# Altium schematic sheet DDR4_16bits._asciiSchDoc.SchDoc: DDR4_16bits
size A3; Date: Not used; ApprovedBy: Not used; CheckedBy: Not used; Author: Not used; CompanyName: STMicroelectronics; DrawnBy: Not used; Engineer: Not used; Organization: Not used; Address1: Not used; Address2: Not used; Address3: Not used; Address4: Not used; DocumentNumber: 6; Revision: Not used; SheetNumber: 6; SheetTotal: 7
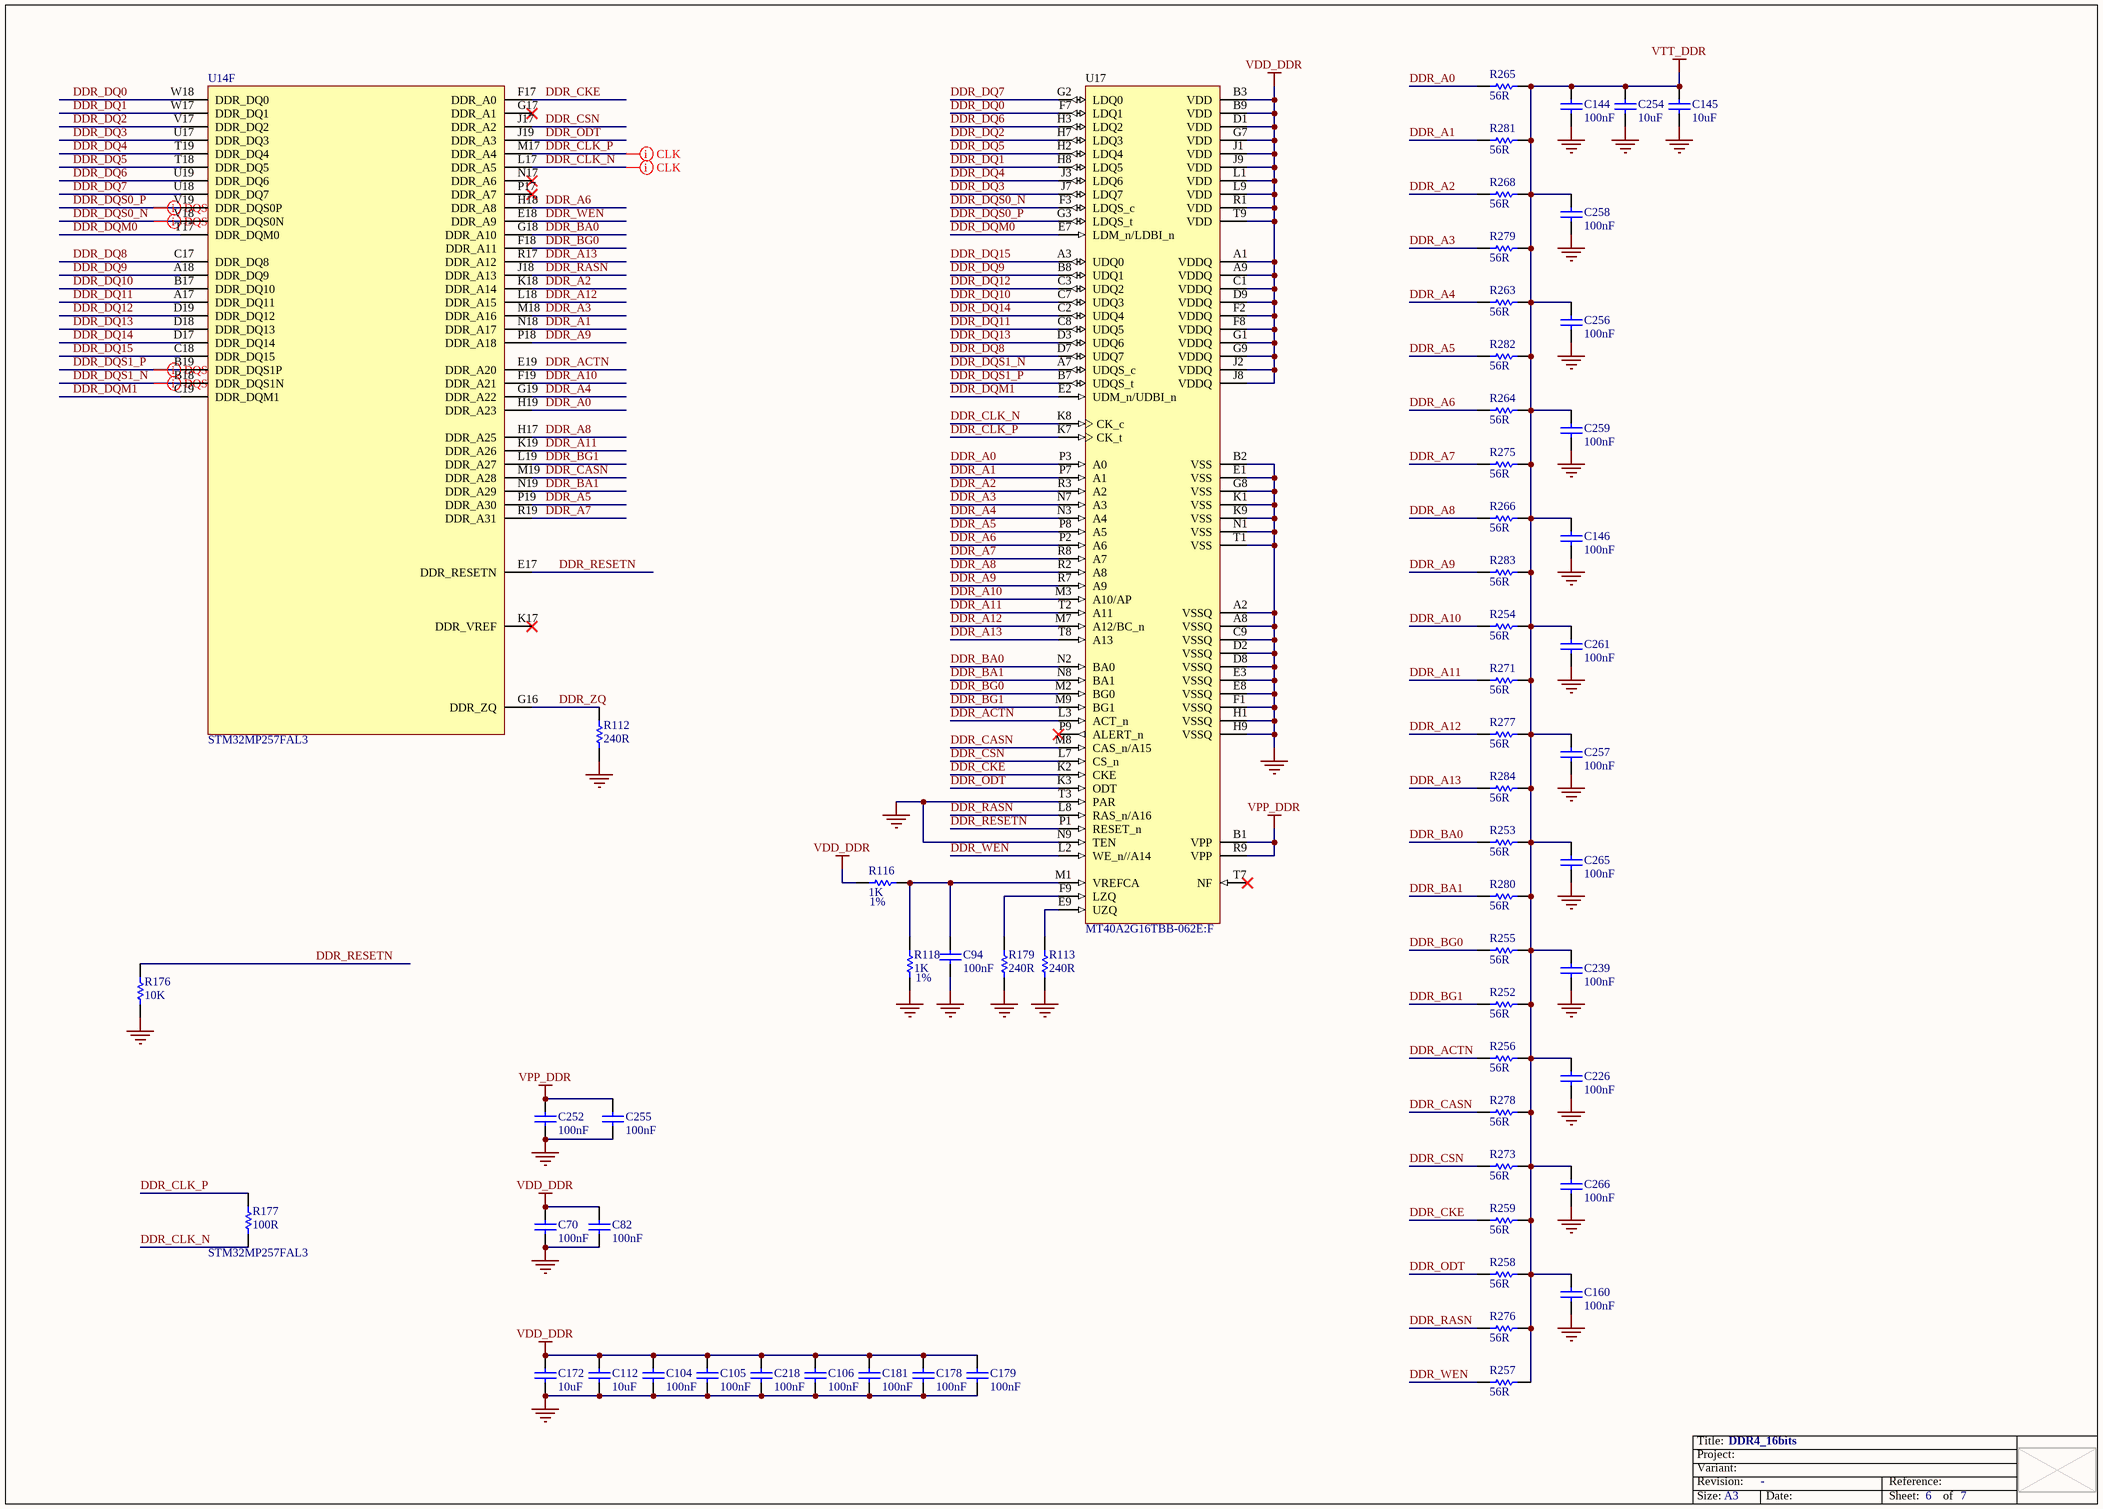
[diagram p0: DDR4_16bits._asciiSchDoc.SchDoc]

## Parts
C70  value 100nF  [C0402]  (hidden comment: Capacitor)
C82  value 100nF  [C0402]  (hidden comment: Capacitor)
C94  value 100nF  [C0402]  (hidden comment: Capacitor)
C104  value 100nF  [C0402]  (hidden comment: Capacitor)
C105  value 100nF  [C0402]  (hidden comment: Capacitor)
C106  value 100nF  [C0402]  (hidden comment: Capacitor)
C112  value 10uF  [C0603]  (hidden comment: Capacitor)
C144  value 100nF  [C0402]  (hidden comment: Capacitor)
C145  value 10uF  [C0402]  (hidden comment: Capacitor)
C146  value 100nF  [C0402]  (hidden comment: Capacitor)
C160  value 100nF  [C0402]  (hidden comment: Capacitor)
C172  value 10uF  [C0603]  (hidden comment: Capacitor)
C178  value 100nF  [C0402]  (hidden comment: Capacitor)
C179  value 100nF  [C0402]  (hidden comment: Capacitor)
C181  value 100nF  [C0402]  (hidden comment: Capacitor)
C218  value 100nF  [C0402]  (hidden comment: Capacitor)
C226  value 100nF  [C0402]  (hidden comment: Capacitor)
C239  value 100nF  [C0402]  (hidden comment: Capacitor)
C252  value 100nF  [C0402]  (hidden comment: Capacitor)
C254  value 10uF  [C0402]  (hidden comment: Capacitor)
C255  value 100nF  [C0402]  (hidden comment: Capacitor)
C256  value 100nF  [C0402]  (hidden comment: Capacitor)
C257  value 100nF  [C0402]  (hidden comment: Capacitor)
C258  value 100nF  [C0402]  (hidden comment: Capacitor)
C259  value 100nF  [C0402]  (hidden comment: Capacitor)
C261  value 100nF  [C0402]  (hidden comment: Capacitor)
C265  value 100nF  [C0402]  (hidden comment: Capacitor)
C266  value 100nF  [C0402]  (hidden comment: Capacitor)
R112  value 240R  [R0201_H0P23]  (hidden comment: Resistor)
R113  value 240R  [R0201_H0P23]  (hidden comment: Resistor)
R116  value 1K  [R0402]  (hidden comment: Resistor)
R118  value 1K  [R0402]  (hidden comment: Resistor)
R176  value 10K  [R0402]  (hidden comment: Resistor)
R177  value 100R  [R0402]  (hidden comment: Resistor)
R179  value 240R  [R0201_H0P23]  (hidden comment: Resistor)
R252  value 56R  [R0402]  (hidden comment: Resistor)
R253  value 56R  [R0402]  (hidden comment: Resistor)
R254  value 56R  [R0402]  (hidden comment: Resistor)
R255  value 56R  [R0402]  (hidden comment: Resistor)
R256  value 56R  [R0402]  (hidden comment: Resistor)
R257  value 56R  [R0402]  (hidden comment: Resistor)
R258  value 56R  [R0402]  (hidden comment: Resistor)
R259  value 56R  [R0402]  (hidden comment: Resistor)
R263  value 56R  [R0402]  (hidden comment: Resistor)
R264  value 56R  [R0402]  (hidden comment: Resistor)
R265  value 56R  [R0402]  (hidden comment: Resistor)
R266  value 56R  [R0402]  (hidden comment: Resistor)
R268  value 56R  [R0402]  (hidden comment: Resistor)
R271  value 56R  [R0402]  (hidden comment: Resistor)
R273  value 56R  [R0402]  (hidden comment: Resistor)
R275  value 56R  [R0402]  (hidden comment: Resistor)
R276  value 56R  [R0402]  (hidden comment: Resistor)
R277  value 56R  [R0402]  (hidden comment: Resistor)
R278  value 56R  [R0402]  (hidden comment: Resistor)
R279  value 56R  [R0402]  (hidden comment: Resistor)
R280  value 56R  [R0402]  (hidden comment: Resistor)
R281  value 56R  [R0402]  (hidden comment: Resistor)
R282  value 56R  [R0402]  (hidden comment: Resistor)
R283  value 56R  [R0402]  (hidden comment: Resistor)
R284  value 56R  [R0402]  (hidden comment: Resistor)
U14  STM32MP257FAL3  [ICC_VFBGA361_10X10_P050]  (part F of 8)
U17  MT40A2G16TBB-062E:F  [ICC_FBGA96_TBB_7P5X13_P080]

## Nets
GND: C70.1 C82.1 C94.1 C104.1 C105.1 C106.1 C112.1 C144.1 C145.1 C146.1 C160.1 C172.1 C178.1 C179.1 C181.1 C218.1 C226.1 C239.1 C252.1 C254.1 C255.1 C256.1 C257.1 C258.1 C259.1 C261.1 C265.1 C266.1 R112.1 R113.1 R118.1 R176.1 R179.1 U17.A2(VSSQ) U17.A8(VSSQ) U17.B2(VSS) U17.C9(VSSQ) U17.D2(VSSQ) U17.D8(VSSQ) U17.E1(VSS) U17.E3(VSSQ) U17.E8(VSSQ) U17.F1(VSSQ) U17.G8(VSS) U17.H1(VSSQ) U17.H9(VSSQ) U17.K1(VSS) U17.K9(VSS) U17.N1(VSS) U17.N9(TEN) U17.T1(VSS) U17.T3(PAR)
VDD_DDR: C70.2 C82.2 C104.2 C105.2 C106.2 C112.2 C172.2 C178.2 C179.2 C181.2 C218.2 R116.1 U17.A1(VDDQ) U17.A9(VDDQ) U17.B3(VDD) U17.B9(VDD) U17.C1(VDDQ) U17.D1(VDD) U17.D9(VDDQ) U17.F2(VDDQ) U17.F8(VDDQ) U17.G1(VDDQ) U17.G7(VDD) U17.G9(VDDQ) U17.J1(VDD) U17.J2(VDDQ) U17.J8(VDDQ) U17.J9(VDD) U17.L1(VDD) U17.L9(VDD) U17.R1(VDD) U17.T9(VDD)
VPP_DDR: C252.2 C255.2 U17.B1(VPP) U17.R9(VPP)
VTT_DDR: C144.2 C145.2 C146.2 C160.2 C226.2 C239.2 C254.2 C256.2 C257.2 C258.2 C259.2 C261.2 C265.2 C266.2 R252.2 R253.2 R254.2 R255.2 R256.2 R257.2 R258.2 R259.2 R263.2 R264.2 R265.2 R266.2 R268.2 R271.2 R273.2 R275.2 R276.2 R277.2 R278.2 R279.2 R280.2 R281.2 R282.2 R283.2 R284.2
DDR_A0: R265.1 U14.H19(DDR_A23) U17.P3(A0)
DDR_A1: R281.1 U14.N18(DDR_A17) U17.P7(A1)
DDR_A2: R268.1 U14.K18(DDR_A14) U17.R3(A2)
DDR_A3: R279.1 U14.M18(DDR_A16) U17.N7(A3)
DDR_A4: R263.1 U14.G19(DDR_A22) U17.N3(A4)
DDR_A5: R282.1 U14.P19(DDR_A30) U17.P8(A5)
DDR_A6: R264.1 U14.H18(DDR_A8) U17.P2(A6)
DDR_A7: R275.1 U14.R19(DDR_A31) U17.R8(A7)
DDR_A8: R266.1 U14.H17(DDR_A25) U17.R2(A8)
DDR_A9: R283.1 U14.P18(DDR_A18) U17.R7(A9)
DDR_A10: R254.1 U14.F19(DDR_A21) U17.M3(A10/AP)
DDR_A11: R271.1 U14.K19(DDR_A26) U17.T2(A11)
DDR_A12: R277.1 U14.L18(DDR_A15) U17.M7(A12/BC_n)
DDR_A13: R284.1 U14.R17(DDR_A12) U17.T8(A13)
DDR_ACTN: R256.1 U14.E19(DDR_A20) U17.L3(ACT_n)
DDR_BA0: R253.1 U14.G18(DDR_A10) U17.N2(BA0)
DDR_BA1: R280.1 U14.N19(DDR_A29) U17.N8(BA1)
DDR_BG0: R255.1 U14.F18(DDR_A11) U17.M2(BG0)
DDR_BG1: R252.1 U14.L19(DDR_A27) U17.M9(BG1)
DDR_CASN: R278.1 U14.M19(DDR_A28) U17.M8(CAS_n/A15)
DDR_CKE: R259.1 U14.F17(DDR_A0) U17.K2(CKE)
DDR_CLK_N: R177.2 U14.L17(DDR_A5) U17.K8(CK_c)
DDR_CLK_P: R177.1 U14.M17(DDR_A4) U17.K7(CK_t)
DDR_CSN: R273.1 U14.J17(DDR_A2) U17.L7(CS_n)
DDR_DQ0: U14.W18(DDR_DQ0) U17.F7(LDQ1)
DDR_DQ1: U14.W17(DDR_DQ1) U17.H8(LDQ5)
DDR_DQ2: U14.V17(DDR_DQ2) U17.H7(LDQ3)
DDR_DQ3: U14.U17(DDR_DQ3) U17.J7(LDQ7)
DDR_DQ4: U14.T19(DDR_DQ4) U17.J3(LDQ6)
DDR_DQ5: U14.T18(DDR_DQ5) U17.H2(LDQ4)
DDR_DQ6: U14.U19(DDR_DQ6) U17.H3(LDQ2)
DDR_DQ7: U14.U18(DDR_DQ7) U17.G2(LDQ0)
DDR_DQ8: U14.C17(DDR_DQ8) U17.D7(UDQ7)
DDR_DQ9: U14.A18(DDR_DQ9) U17.B8(UDQ1)
DDR_DQ10: U14.B17(DDR_DQ10) U17.C7(UDQ3)
DDR_DQ11: U14.A17(DDR_DQ11) U17.C8(UDQ5)
DDR_DQ12: U14.D19(DDR_DQ12) U17.C3(UDQ2)
DDR_DQ13: U14.D18(DDR_DQ13) U17.D3(UDQ6)
DDR_DQ14: U14.D17(DDR_DQ14) U17.C2(UDQ4)
DDR_DQ15: U14.C18(DDR_DQ15) U17.A3(UDQ0)
DDR_DQM0: U14.T17(DDR_DQM0) U17.E7(LDM_n/LDBI_n)
DDR_DQM1: U14.C19(DDR_DQM1) U17.E2(UDM_n/UDBI_n)
DDR_DQS0_N: U14.V18(DDR_DQS0N) U17.F3(LDQS_c)
DDR_DQS0_P: U14.V19(DDR_DQS0P) U17.G3(LDQS_t)
DDR_DQS1_N: U14.B18(DDR_DQS1N) U17.A7(UDQS_c)
DDR_DQS1_P: U14.B19(DDR_DQS1P) U17.B7(UDQS_t)
DDR_ODT: R258.1 U14.J19(DDR_A3) U17.K3(ODT)
DDR_RASN: R276.1 U14.J18(DDR_A13) U17.L8(RAS_n/A16)
DDR_RESETN: R176.2 U14.E17(DDR_RESETN) U17.P1(RESET_n)
DDR_WEN: R257.1 U14.E18(DDR_A9) U17.L2(WE_n//A14)
DDR_ZQ: R112.2 U14.G16(DDR_ZQ)
NetC94_2: C94.2 R116.2 R118.2 U17.M1(VREFCA)
NetR113_2: R113.2 U17.E9(UZQ)
NetR179_2: R179.2 U17.F9(LZQ)

Not connected (* = marked no-connect by the designer): U14 G17(DDR_A1)* K17(DDR_VREF)* N17(DDR_A6)* P17(DDR_A7)*; U17 P9(ALERT_n)* T7(NF)*

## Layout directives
differential pair: DDR_CLK_N, DDR_CLK_P, DDR_DQS0_N, DDR_DQS0_P, DDR_DQS1_N, DDR_DQS1_P

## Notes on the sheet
- (near R116) 1%
- (near R118) 1%

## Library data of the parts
C70 C82 C94 C104-C106 C144 C146 C160 C178 C179 C181 C218 C226 C239 C252 C255-C259 C261 C265 C266 = MCD-00006: Capacitor, MLCC, 100nF, 16V, X7R, +/-10%, 0402, T=0.5mm; Part_Preference: Recommended; Manufacturer: YAGEO; Manufacturer_Part_Number: CC0402KRX7R7BB104; Alternate_Manufacturer: MURATA; Alternate_Manufacturer_Part_Number: GCM155R71C104KA55D; Order_Code_RS: 616-9701
C112 C172 = MCD-01341: Capacitor, MLCC, 10uF, 6V3, X5R, +/-20%, 0603, T=0,8mm; Part_Preference: Recommended; Manufacturer: MURATA; Manufacturer_Part_Number: GRM188R60J106ME47D; Alternate_Manufacturer_Part_Number: GRM188R60J106ME84D
C145 C254 = MCD-03140: Capacitor, MLCC, 10uF, 6.3V, X5R, +/-20%, 0402, T=0.5mm; Part_Preference: Recommended; Manufacturer: MURATA; Manufacturer_Part_Number: GRM155R60J106ME05D; ShowFields: YES; ID: 5256
R112 R113 R179 = MCD-02253: Resistor,240R,0201,1%,1/20W; Part_Preference: Recommended; Manufacturer: YAGEO; Manufacturer_Part_Number: RC0201FR-07240RL
R116 R118 = MCD-00061: Resistor, 1K, 0402, +/-1%,1/16W; Part_Preference: Recommended; Manufacturer: YAGEO; Manufacturer_Part_Number: RC0402FR-071KL; Order_Code_RS: 9239235; Component_Country_Of_Origin: China; ShowFields: YES; ID: 2532
R176 = MCD-00053: Resistor,10K,0402,1%,1/16W; BMS_Part_Number: 9131590; Part_Preference: Recommended; Manufacturer: YAGEO; Manufacturer_Part_Number: RC0402FR-0710KL
R177 = MCD-01819: Resistor,100R,0402,0,5%,1/16W,±100ppm/°C; Part_Preference: Recommended; Manufacturer: YAGEO; Manufacturer_Part_Number: RC0402DR-07100RL
R252-R259 R263-R266 R268 R271 R273 R275-R284 = MCD-00054: Resistor, 56R, 0402, +/-1%, 1/16W; Part_Preference: Recommended; Manufacturer: YAGEO; Manufacturer_Part_Number: RC0402FR-0756RL
U14 = MCD-03768: MPU, dual core ARM cortex-A35 64-bit + M33 32-bit, 808KB SRAM, With Crypto; Part_Type: IC; Part_Preference: Recommended; Manufacturer: STMICROELECTRONICS; Component_Country_Of_Origin: Unknown; ShowFields: YES; ID: 5884
U17 = MCD-04020: Memory, DDR4 SDRAM, 1V2, 32Gbit, 1.6GHz, FBGA96; Part_Type: IC; Part_Preference: Recommended; Manufacturer: MICRON; ShowFields: YES; ID: 6136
